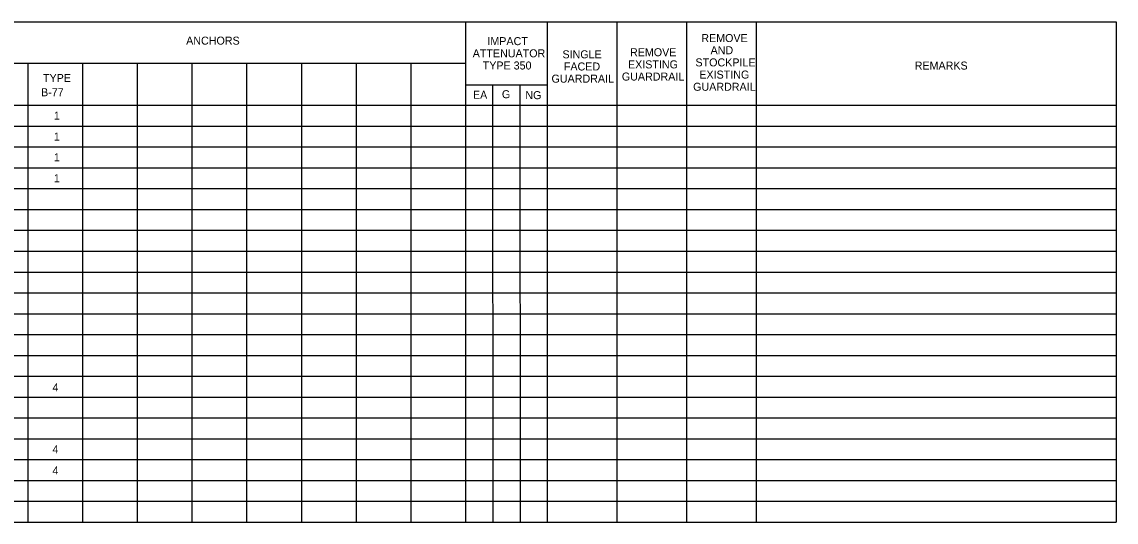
# Model space of a CAD drawing. Extents: x 649560 to 652923, y 1843307 to 1844407.
# Drawn here: x 650404 to 651060, y 1843973 to 1844273 of the extents above; entities that cross this region are included whole.
import ezdxf

# ---------------------------------------------------------------- set-up
doc = ezdxf.new("R2010")
doc.units = 0
doc.layers.add('P_RDY_Edge_of_Travel', color=7, linetype='Continuous')

msp = doc.modelspace()

# ---------------------------------------------------------------- linework, layer by layer
at = {"layer": 'P_RDY_Edge_of_Travel'}
for p, q in [((649560.05, 1844272.72), (651060.05, 1844272.72)), ((650670, 1844272.72), (650670, 1843972.72)), ((650718.85, 1844272.72), (650718.85, 1843972.72)), ((650760.65, 1844272.72), (650760.65, 1843972.72)), ((650802.45, 1844272.72), (650802.45, 1843972.72)), ((650844.3, 1844272.72), (650844.3, 1843972.72)), ((651060.05, 1844272.72), (651060.05, 1843972.72)), ((650670, 1844247.72), (650192.85, 1844247.72)), ((650407.5, 1844247.72), (650407.5, 1843972.72)), ((650440.3, 1844247.72), (650440.3, 1843972.72)), ((650473.15, 1844247.72), (650473.15, 1843972.72)), ((650505.95, 1844247.72), (650505.95, 1843972.72)), ((650538.75, 1844247.72), (650538.75, 1843972.72)), ((650571.55, 1844247.72), (650571.55, 1843972.72)), ((650604.4, 1844247.72), (650604.4, 1843972.72)), ((650637.2, 1844247.72), (650637.2, 1843972.72)), ((650670, 1844234.97), (650718.6, 1844234.97)), ((650686.25, 1844234.97), (650686.4, 1843972.72)), ((650702.6, 1844234.97), (650702.75, 1843972.72)), ((649560.05, 1844222.72), (651060.05, 1844222.72)), ((649560.05, 1844210.22), (651060.05, 1844210.22)), ((649560.05, 1844197.72), (651060.05, 1844197.72)), ((649560.05, 1844185.22), (651060.05, 1844185.22)), ((649560.05, 1844172.72), (651060.05, 1844172.72)), ((649560.05, 1844160.22), (651060.05, 1844160.22)), ((649560.05, 1844147.72), (651060.05, 1844147.72)), ((649560.05, 1844135.22), (651060.05, 1844135.22)), ((649560.05, 1844122.72), (651060.05, 1844122.72)), ((649560.05, 1844110.22), (651060.05, 1844110.22)), ((649560.05, 1844097.72), (651060.05, 1844097.72)), ((649560.05, 1844085.22), (651060.05, 1844085.22)), ((649560.05, 1844085.22), (651060.05, 1844085.22)), ((649560.05, 1844072.72), (651060.05, 1844072.72)), ((649560.05, 1844060.22), (651060.05, 1844060.22)), ((649560.05, 1844047.72), (651060.05, 1844047.72)), ((649560.05, 1844035.22), (651060.05, 1844035.22)), ((649560.05, 1844022.72), (651060.05, 1844022.72)), ((649560.05, 1844010.22), (651060.05, 1844010.22)), ((649560.05, 1843997.72), (651060.05, 1843997.72)), ((649560.05, 1843985.22), (651060.05, 1843985.22)), ((649560.05, 1843972.72), (651060.05, 1843972.72))]:
    msp.add_line(p, q, dxfattribs=at)

# ---------------------------------------------------------------- texts
for s, p in [('REMOVE', (650811.35, 1844260.62)), ('ANCHORS', (650502.5, 1844259.07)), ('IMPACT', (650683.1, 1844258.77)), ('ATTENUATOR', (650674.3, 1844251.47)), ('SINGLE', (650728.1, 1844250.87)), ('REMOVE', (650768.6, 1844252.12)), ('AND', (650816.9, 1844253.32)), ('TYPE 350', (650680.3, 1844244.17)), ('FACED', (650728.95, 1844243.57)), ('EXISTING', (650767.4, 1844244.82)), ('STOCKPILE', (650807.85, 1844246.02)), ('REMARKS', (650939.3, 1844244.12)), ('TYPE', (650416.66, 1844236.67)), ('GUARDRAIL', (650721.55, 1844236.27)), ('GUARDRAIL', (650763.7, 1844237.52)), ('EXISTING', (650810.15, 1844238.72)), ('B-77', (650415.5, 1844228.12)), ('GUARDRAIL', (650806.45, 1844231.42)), ('EA', (650674.45, 1844226.57)), ('G', (650691.8, 1844226.92)), ('NG', (650705.85, 1844226.37)), ('1', (650423.17, 1844214.07)), ('1', (650423.17, 1844201.57)), ('1', (650423.17, 1844189.07)), ('1', (650423.17, 1844176.57)), ('4', (650422.37, 1844051.11)), ('4', (650422.37, 1844014.07)), ('4', (650422.37, 1844001.29))]:
    msp.add_text(s, height=4.8, dxfattribs=at).set_placement(p)

doc.saveas('drawing.dxf')
